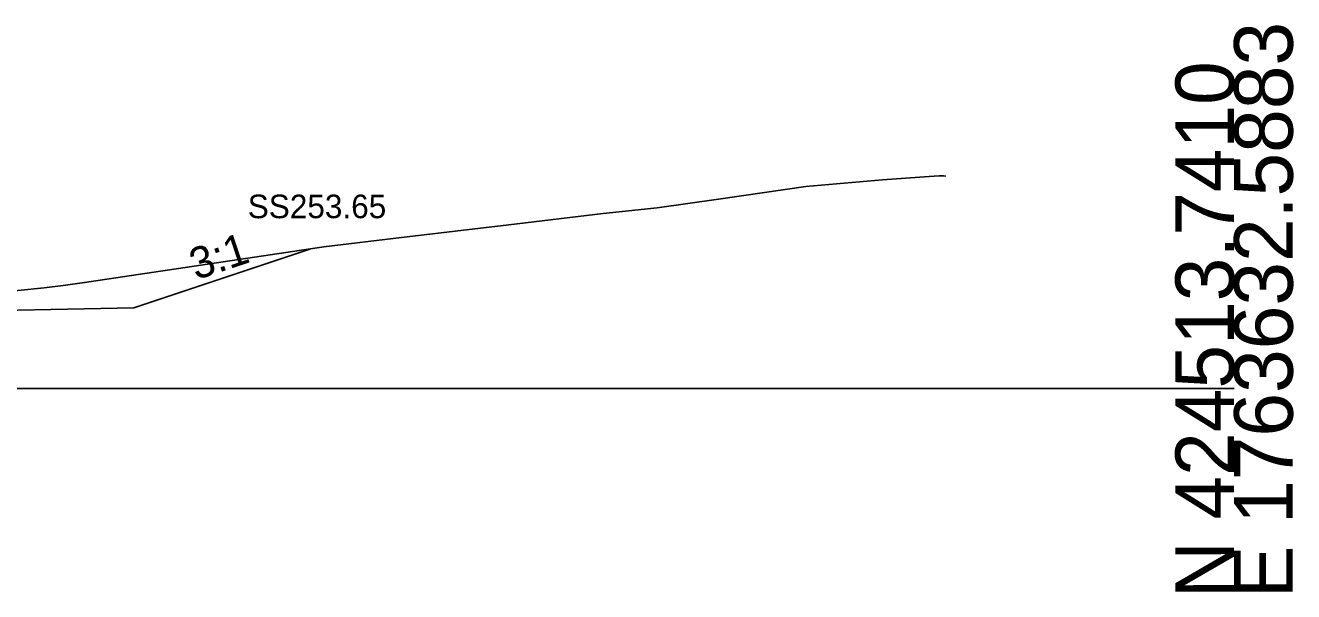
# Model space of a CAD drawing. Extents: x -26 to 3203, y -11010 to 4024.
# Drawn here: x 2142.3 to 2202.8, y 490.3 to 517.3 of the extents above; entities that cross this region are included whole.
import ezdxf

# ---------------------------------------------------------------- set-up
doc = ezdxf.new("R2010")
doc.units = 0
for name, color, linetype in [('Exist Cross Section Cell', 7, 'Continuous'), ('Exist XS Ground Line', 7, 'Continuous'), ('Prop CMT Slope Grass', 7, 'Continuous'), ('Prop XS Side Slope Text', 7, 'Continuous'), ('Prop XS SS Elevation Text', 7, 'Continuous'), ('Scratch_Level_0', 7, 'Continuous')]:
    doc.layers.add(name, color=color, linetype=linetype)

msp = doc.modelspace()

# ---------------------------------------------------------------- linework, layer by layer
at = {"layer": 'Exist Cross Section Cell'}
msp.add_line((2100, 500), (2200, 500), dxfattribs=at)
at = {"layer": 'Exist XS Ground Line'}
msp.add_lwpolyline([(2139.45, 504.411), (2143.236, 504.799), (2144.135, 504.912), (2145.157, 505.061), (2156.564, 506.749), (2160.282, 507.2), (2165.391, 507.797), (2169.893, 508.338), (2172.476, 508.622), (2175.407, 509.03), (2179.561, 509.628), (2183.221, 509.948), (2185.458, 510.111), (2185.927, 510.143), (2186.131, 510.136), (2186.245, 510.131)], dxfattribs=at)
msp.add_lwpolyline([(2139.45, 504.411), (2143.236, 504.799), (2144.135, 504.912), (2145.157, 505.061), (2156.564, 506.749), (2160.282, 507.2), (2165.391, 507.797), (2169.893, 508.338), (2172.476, 508.622), (2175.407, 509.03), (2179.561, 509.628), (2183.221, 509.948), (2185.458, 510.111), (2185.927, 510.143), (2186.131, 510.136), (2186.245, 510.131)], dxfattribs=at)
msp.add_lwpolyline([(2139.45, 504.411), (2143.236, 504.799), (2144.135, 504.912), (2145.157, 505.061), (2156.564, 506.749), (2160.282, 507.2), (2165.391, 507.797), (2169.893, 508.338), (2172.476, 508.622), (2175.407, 509.03), (2179.561, 509.628), (2183.221, 509.948), (2185.458, 510.111), (2185.927, 510.143), (2186.131, 510.136), (2186.245, 510.131)], dxfattribs=at)
msp.add_lwpolyline([(2139.45, 504.411), (2143.236, 504.799), (2144.135, 504.912), (2145.157, 505.061), (2156.564, 506.749), (2160.282, 507.2), (2165.391, 507.797), (2169.893, 508.338), (2172.476, 508.622), (2175.407, 509.03), (2179.561, 509.628), (2183.221, 509.948), (2185.458, 510.111), (2185.927, 510.143), (2186.131, 510.136), (2186.245, 510.131)], dxfattribs=at)
msp.add_lwpolyline([(2139.45, 504.411), (2143.236, 504.799), (2144.135, 504.912), (2145.157, 505.061), (2156.564, 506.749), (2160.282, 507.2), (2165.391, 507.797), (2169.893, 508.338), (2172.476, 508.622), (2175.407, 509.03), (2179.561, 509.628), (2183.221, 509.948), (2185.458, 510.111), (2185.927, 510.143), (2186.131, 510.136), (2186.245, 510.131)], dxfattribs=at)
at = {"layer": 'Prop CMT Slope Grass'}
msp.add_lwpolyline([(2138.001, 503.662), (2147.501, 503.852), (2155.897, 506.65)], dxfattribs=at)

# ---------------------------------------------------------------- texts
at = {"layer": 'Exist Cross Section Cell'}
for s, p in [('E 1763632.5883', (2202.8, 490)), ('N 424513.7410', (2200, 490))]:
    msp.add_text(s, height=2.8, rotation=90, dxfattribs=at).set_placement(p)
at = {"layer": 'Prop XS Side Slope Text'}
msp.add_text('3:1', height=1.5, rotation=18.43493, dxfattribs=at).set_placement((2150.476, 505.16))
at = {"layer": 'Prop XS SS Elevation Text'}
msp.add_text('SS253.65', height=1.125, dxfattribs=at).set_placement((2152.941, 508.121))
at = {"layer": 'Scratch_Level_0'}
for s, p in [('Exterior Boundary', (2155.739, 506.64)), ('RT_Slope_Cut', (2155.793, 506.64)), ('RT_CSLP_Pnt', (2147.402, 503.842))]:
    msp.add_text(s, height=0.02, dxfattribs=at).set_placement(p)

doc.saveas('drawing.dxf')
